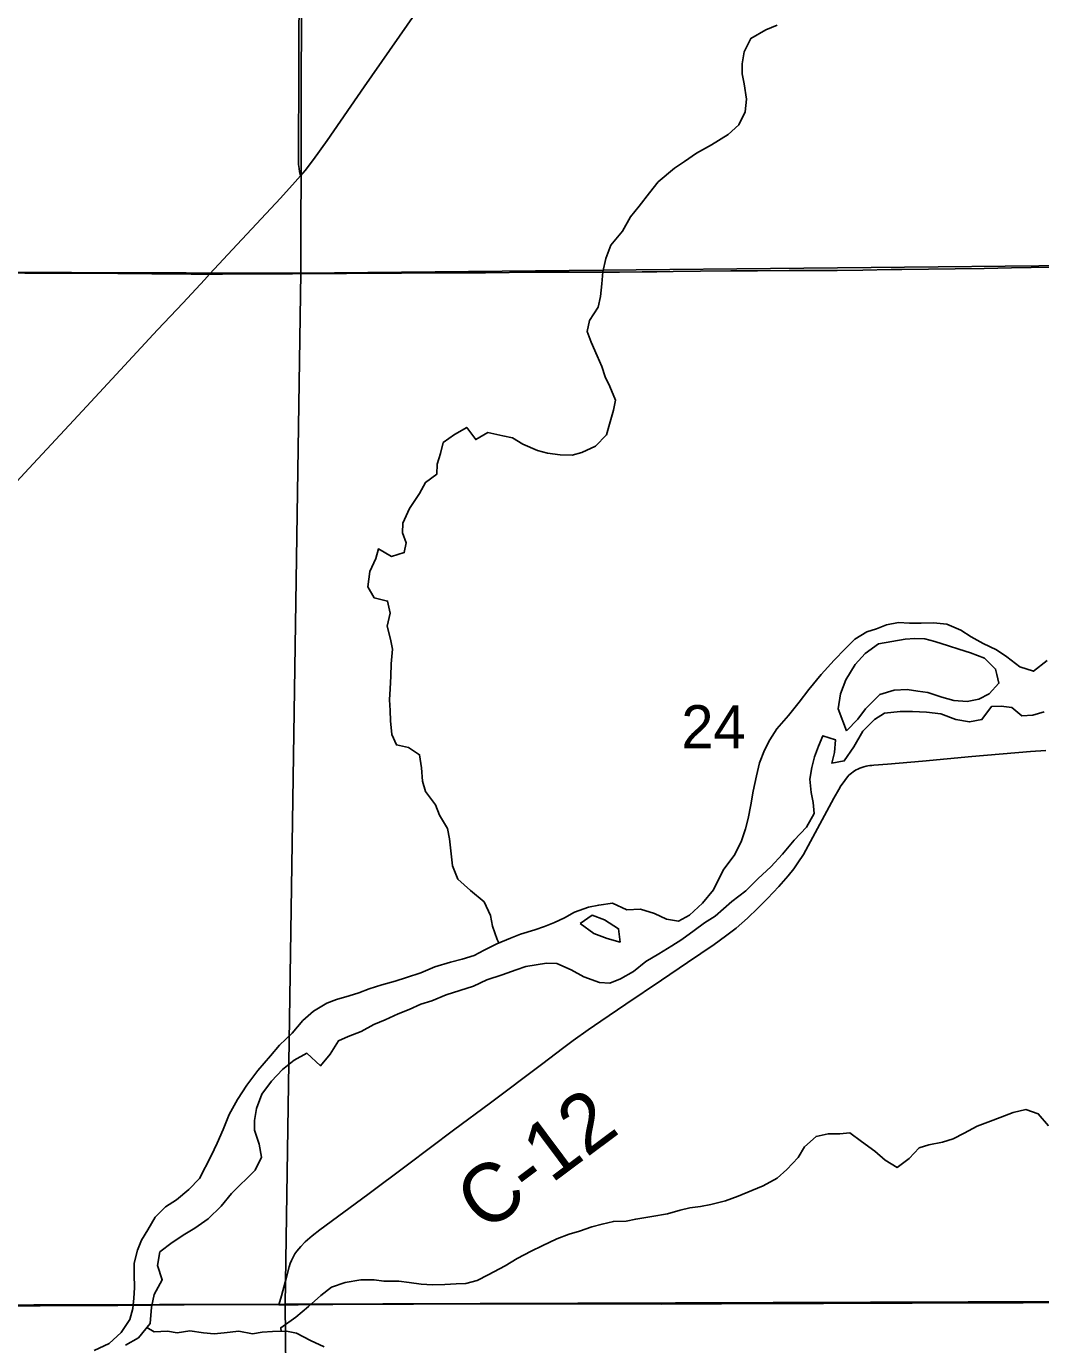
# Model space of a CAD drawing. Extents: x 0 to 34, y 0 to 22.
# Drawn here: x 7.827 to 8.318, y 15.384 to 16.023 of the extents above; entities that cross this region are included whole.
import ezdxf

# ---------------------------------------------------------------- set-up
doc = ezdxf.new("R2010")
doc.units = 0
for name, color, linetype in [('GM_X_County_Road', 7, 'Continuous'), ('GM_X_County_Road_Text', 7, 'Continuous'), ('GM_X_Major_River', 7, 'Continuous'), ('GM_X_Minor_River', 7, 'Continuous'), ('GM_X_Section', 7, 'Continuous'), ('GM_X_Section_Text', 7, 'Continuous'), ('GM_X_State_Route', 7, 'Continuous'), ('GM_X_Township_Road', 7, 'Continuous')]:
    doc.layers.add(name, color=color, linetype=linetype)

msp = doc.modelspace()

# ---------------------------------------------------------------- linework, layer by layer
at = {"layer": 'GM_X_County_Road'}
for points in [[(7.94893, 15.40341), (7.95008, 15.40765), (7.95252, 15.4167), (7.95388, 15.42176), (7.95439, 15.42337), (7.95494, 15.42484), (7.95542, 15.42586), (7.95593, 15.42682), (7.95665, 15.42805), (7.95754, 15.42931), (7.95849, 15.43047), (7.95952, 15.43167), (7.96167, 15.43386), (7.96501, 15.43676), (7.96866, 15.43967), (7.99189, 15.45686), (8.01111, 15.47111), (8.03348, 15.4879), (8.05145, 15.50124), (8.07602, 15.51975), (8.08691, 15.52801), (8.0914, 15.53135), (8.09872, 15.53659), (8.10487, 15.54082), (8.11698, 15.54898), (8.13419, 15.5607), (8.14685, 15.56917), (8.1597, 15.57784), (8.16525, 15.58186), (8.17029, 15.58587), (8.1758, 15.59062), (8.18083, 15.59547), (8.18558, 15.60011), (8.19106, 15.60605), (8.19553, 15.61122), (8.19822, 15.61463), (8.20023, 15.61739), (8.20295, 15.62156), (8.20866, 15.63207), (8.21319, 15.6404), (8.21772, 15.64879), (8.22011, 15.65302), (8.22113, 15.65472), (8.22215, 15.65622), (8.22302, 15.65742), (8.22385, 15.65851), (8.22442, 15.65926), (8.225, 15.65985), (8.2256, 15.66038), (8.22627, 15.66094), (8.22701, 15.66149), (8.22771, 15.66199), (8.22849, 15.66246), (8.22932, 15.66289), (8.23026, 15.66334), (8.23117, 15.66366), (8.23219, 15.66397), (8.23332, 15.66427), (8.2342, 15.66444), (8.23511, 15.66457), (8.23607, 15.66466), (8.23706, 15.66473), (8.24359, 15.66523), (8.26066, 15.66677), (8.28449, 15.66903), (8.31299, 15.67131), (8.32039, 15.67192)], [(7.58622, 15.40079), (7.6173, 15.40146), (7.62818, 15.40159), (7.64528, 15.40177), (7.65552, 15.40181), (7.6717, 15.40199), (7.70553, 15.40236), (7.7254, 15.40252), (7.74529, 15.40247), (7.76115, 15.40249), (7.78539, 15.40253), (7.80342, 15.40249), (7.83325, 15.40291), (7.84848, 15.40298), (7.87086, 15.40303), (7.91902, 15.40347), (7.92896, 15.40346), (7.94893, 15.40341)], [(7.94893, 15.40341), (7.95818, 15.40339), (7.97496, 15.40349), (8.00013, 15.40368), (8.01412, 15.40375), (8.02313, 15.4038), (8.06011, 15.40377), (8.08684, 15.40376), (8.13409, 15.40374), (8.14652, 15.40384), (8.1633, 15.40388), (8.18412, 15.40395), (8.21272, 15.40404), (8.25561, 15.40413), (8.28637, 15.40433), (8.30937, 15.4044), (8.33205, 15.4045)]]:
    msp.add_lwpolyline(points, dxfattribs=at)
at = {"layer": 'GM_X_Major_River'}
for points in [[(8.32105, 15.71539), (8.31438, 15.7103), (8.30775, 15.71241), (8.3015, 15.71719), (8.29639, 15.72062), (8.28996, 15.72369), (8.28427, 15.72694), (8.27916, 15.73019), (8.27234, 15.73306), (8.26589, 15.73366), (8.26001, 15.73349), (8.25431, 15.73352), (8.249, 15.73392), (8.24311, 15.73281), (8.23836, 15.73074), (8.23361, 15.72943), (8.2279, 15.72585), (8.22314, 15.72113), (8.2178, 15.71565), (8.21151, 15.70865), (8.20559, 15.70147), (8.20082, 15.69522), (8.19567, 15.6888), (8.19014, 15.68237), (8.1867, 15.67707), (8.18402, 15.67196), (8.18172, 15.66589), (8.18017, 15.65964), (8.17862, 15.65224), (8.17746, 15.6456), (8.1761, 15.63897), (8.17494, 15.63385), (8.17283, 15.6276), (8.16938, 15.62097), (8.16442, 15.61435), (8.16174, 15.60943), (8.15944, 15.60431), (8.1541, 15.59788), (8.14781, 15.59203), (8.14249, 15.5892), (8.13661, 15.59018), (8.13074, 15.59286), (8.1241, 15.59497), (8.11746, 15.59462), (8.11045, 15.59788), (8.1038, 15.59696), (8.09886, 15.59603), (8.09202, 15.59359), (8.08727, 15.59077), (8.08232, 15.58851), (8.07757, 15.58663), (8.07282, 15.58494), (8.06598, 15.58289), (8.06103, 15.58101), (8.05438, 15.57819), (8.04829, 15.57518), (8.04354, 15.57254), (8.03765, 15.57086), (8.03195, 15.56937), (8.02435, 15.56712), (8.01769, 15.56412), (8.01066, 15.56187), (8.00515, 15.56018), (7.99869, 15.55831)], [(8.29664, 15.70861), (8.29598, 15.71133), (8.29068, 15.71666), (8.28386, 15.71916), (8.27818, 15.72089), (8.27325, 15.72262), (8.26661, 15.72474), (8.26169, 15.7259), (8.25694, 15.72611), (8.25219, 15.72575), (8.23928, 15.72353), (8.23281, 15.71881), (8.22804, 15.71352), (8.22345, 15.70613), (8.22096, 15.69931), (8.21979, 15.69211), (8.22373, 15.68146)], [(8.22373, 15.68146), (8.22926, 15.68713), (8.23307, 15.69205), (8.23993, 15.69904), (8.24697, 15.7011), (8.25323, 15.70145), (8.25835, 15.70067), (8.26328, 15.69989), (8.26992, 15.69777), (8.27579, 15.69604), (8.28224, 15.69563), (8.28794, 15.69675), (8.29289, 15.69938), (8.29766, 15.70449), (8.29664, 15.70861)], [(8.02295, 15.55062), (8.02998, 15.55344), (8.04309, 15.55774), (8.04956, 15.56075), (8.05697, 15.56319), (8.06381, 15.56563), (8.06857, 15.56731), (8.07844, 15.56879), (8.08357, 15.56877), (8.09039, 15.5657), (8.09663, 15.56226), (8.10421, 15.55957), (8.10915, 15.55917), (8.11428, 15.56124), (8.12056, 15.56482), (8.12665, 15.56972), (8.13293, 15.5733), (8.13921, 15.57726), (8.14397, 15.58028), (8.15006, 15.58462), (8.15501, 15.58839), (8.16015, 15.59159), (8.16834, 15.59877), (8.175, 15.60387), (8.1811, 15.60991), (8.1872, 15.61558), (8.19273, 15.62163), (8.19845, 15.62844), (8.20436, 15.63467), (8.20819, 15.6413), (8.20764, 15.64661), (8.20671, 15.65155), (8.20598, 15.65801), (8.20695, 15.6637), (8.2083, 15.66881), (8.21022, 15.67393), (8.21233, 15.67904), (8.2184, 15.67712), (8.21799, 15.67086), (8.21664, 15.66574), (8.22272, 15.66685), (8.2273, 15.67367), (8.2317, 15.68124), (8.23742, 15.68691), (8.24217, 15.68992), (8.24977, 15.69084), (8.25584, 15.69081), (8.26248, 15.69041), (8.2695, 15.68962), (8.2767, 15.68693), (8.28334, 15.68576), (8.28942, 15.68687), (8.294, 15.69312), (8.29875, 15.69329), (8.30387, 15.6927), (8.30879, 15.68869), (8.3141, 15.68905), (8.31961, 15.69054)], [(8.11373, 15.58288), (8.11343, 15.58553), (8.10662, 15.58992), (8.10055, 15.59204), (8.09485, 15.58808)], [(8.09485, 15.58808), (8.10147, 15.5833), (8.10791, 15.58081), (8.11417, 15.57908), (8.11373, 15.58288)], [(7.99869, 15.55831), (7.99261, 15.55644), (7.98766, 15.55456), (7.98291, 15.55307), (7.97683, 15.55119), (7.97208, 15.54951), (7.96561, 15.54555), (7.96047, 15.54102), (7.95532, 15.53496), (7.94922, 15.52911), (7.94483, 15.524), (7.93873, 15.51682), (7.93338, 15.50982), (7.9288, 15.50282), (7.92479, 15.49562), (7.92191, 15.48823), (7.91903, 15.4816), (7.91616, 15.47554), (7.91042, 15.46456), (7.90527, 15.45927), (7.89937, 15.45417), (7.89404, 15.45078), (7.8889, 15.44586), (7.88545, 15.43962), (7.8824, 15.43469), (7.88048, 15.42977), (7.87874, 15.42351), (7.87872, 15.4182), (7.87888, 15.41156), (7.87867, 15.40662), (7.87808, 15.4015), (7.87673, 15.39619), (7.87253, 15.38995), (7.86662, 15.38466), (7.8594, 15.38128)], [(7.87459, 15.38387), (7.88087, 15.38745), (7.88659, 15.39425), (7.88719, 15.40222), (7.88855, 15.40829), (7.89237, 15.41549), (7.89013, 15.42233), (7.89129, 15.42896), (7.89719, 15.43349), (7.90329, 15.43764), (7.90823, 15.44047), (7.9147, 15.44499), (7.92099, 15.45123), (7.92595, 15.45728), (7.93739, 15.46862), (7.94045, 15.47487), (7.93934, 15.48114), (7.93709, 15.48798), (7.93711, 15.49272), (7.93808, 15.49841), (7.94058, 15.50542), (7.94535, 15.51167), (7.95069, 15.51734), (7.95621, 15.52187), (7.96249, 15.52526), (7.9691, 15.51916), (7.97368, 15.52483), (7.9777, 15.53126), (7.98245, 15.53333), (7.98872, 15.53577), (7.99481, 15.53916), (8.00032, 15.54142), (8.0066, 15.54424), (8.01192, 15.54649), (8.01763, 15.54893), (8.02295, 15.55062)]]:
    msp.add_lwpolyline(points, dxfattribs=at)
at = {"layer": 'GM_X_Minor_River'}
for points in [[(8.05546, 15.57865), (8.05458, 15.58028), (8.05233, 15.58674), (8.0514, 15.59187), (8.04839, 15.59852), (8.04177, 15.60405), (8.03553, 15.60958), (8.0329, 15.61605), (8.03217, 15.62326), (8.03144, 15.62915), (8.03051, 15.63409), (8.02674, 15.64055), (8.02468, 15.6455), (8.01996, 15.65197), (8.01846, 15.6571), (8.01792, 15.66355), (8.017, 15.66982), (8.0117, 15.67326), (8.00582, 15.67461), (8.00356, 15.67956), (8.00302, 15.6862), (8.00285, 15.69133), (8.00249, 15.69645), (8.00271, 15.70176), (8.00311, 15.70783), (8.00333, 15.71391), (8.00393, 15.72092), (8.003, 15.72586), (8.00132, 15.73213), (8.00286, 15.73839), (8.00156, 15.74428), (7.99511, 15.74582), (7.99191, 15.75115), (7.99289, 15.75855), (7.99576, 15.7648), (7.99711, 15.76953), (8.00336, 15.7659), (8.00963, 15.76777), (8.0106, 15.77251), (8.00872, 15.77727), (8.00893, 15.78201), (8.01218, 15.78902), (8.01696, 15.7964), (8.01983, 15.8017), (8.02535, 15.80566), (8.02556, 15.81059), (8.0271, 15.81571), (8.02845, 15.82102), (8.03397, 15.82498), (8.03987, 15.82837), (8.04421, 15.82247), (8.05011, 15.82586), (8.05731, 15.82431), (8.06205, 15.82334), (8.06698, 15.82028), (8.07418, 15.81722), (8.07891, 15.81587), (8.08517, 15.81508), (8.09087, 15.81487), (8.09562, 15.81618), (8.10227, 15.81937), (8.10761, 15.82485), (8.10896, 15.82997), (8.11089, 15.8368), (8.11186, 15.84154), (8.10923, 15.84819), (8.10697, 15.85294), (8.10528, 15.85788), (8.10303, 15.86302), (8.10021, 15.86967), (8.09814, 15.8748), (8.0993, 15.88011), (8.10351, 15.88655), (8.10467, 15.89186), (8.10526, 15.89793), (8.10586, 15.9038), (8.10721, 15.91025), (8.10971, 15.91669), (8.11524, 15.9235), (8.11926, 15.93031), (8.12345, 15.93561), (8.12841, 15.94204), (8.13261, 15.94734), (8.14042, 15.95394), (8.14537, 15.95715), (8.15108, 15.9613), (8.1585, 15.96525), (8.16649, 15.97034), (8.17164, 15.97487), (8.1747, 15.98131), (8.1753, 15.98738), (8.17419, 15.99479), (8.17326, 15.99973), (8.17328, 16.00447), (8.17426, 16.01035), (8.17751, 16.01679), (8.18474, 16.02093), (8.19025, 16.02318)], [(7.95001, 15.3905), (7.94978, 15.39228), (7.95702, 15.39737), (7.9633, 15.40247), (7.96921, 15.40795), (7.97435, 15.41191), (7.981, 15.41416), (7.9886, 15.41546), (7.99505, 15.41543), (7.99979, 15.41484), (8.007, 15.41481), (8.01194, 15.41422), (8.01782, 15.41343), (8.02332, 15.41303), (8.0292, 15.4132), (8.03471, 15.41355), (8.03945, 15.41372), (8.04496, 15.41522), (8.05029, 15.41785), (8.05847, 15.42218), (8.06437, 15.42576), (8.07102, 15.42934), (8.07635, 15.43197), (8.08357, 15.43536), (8.08947, 15.43761), (8.09441, 15.43911), (8.10049, 15.44117), (8.10543, 15.44248), (8.11094, 15.44378), (8.11701, 15.44395), (8.12176, 15.44487), (8.12955, 15.44617), (8.13715, 15.44747), (8.14323, 15.44915), (8.14798, 15.45027), (8.1531, 15.451), (8.15804, 15.45193), (8.16526, 15.4538), (8.17134, 15.45605), (8.178, 15.45868), (8.18351, 15.46093), (8.19017, 15.4647), (8.19493, 15.46885), (8.20046, 15.47471), (8.20352, 15.47982), (8.20905, 15.48492), (8.21493, 15.48623), (8.22063, 15.4862), (8.22537, 15.48675), (8.23105, 15.48255), (8.23748, 15.47778), (8.24259, 15.47339), (8.24827, 15.46995), (8.25417, 15.47429), (8.25894, 15.4794), (8.26369, 15.48089), (8.27034, 15.48219), (8.27547, 15.48369), (8.28079, 15.48651), (8.28707, 15.4899), (8.29353, 15.49234), (8.29829, 15.49403), (8.30456, 15.49647), (8.31064, 15.49796), (8.3167, 15.49585), (8.32161, 15.49013)], [(7.885, 15.39236), (7.88847, 15.39026), (7.89493, 15.39061), (7.89967, 15.38983), (7.90575, 15.39076), (7.91238, 15.38978), (7.91751, 15.38938), (7.92244, 15.38974), (7.92947, 15.39066), (7.93611, 15.3893), (7.94085, 15.39004), (7.94579, 15.3904), (7.95262, 15.39056), (7.95736, 15.38959), (7.96418, 15.38615), (7.97081, 15.38308)]]:
    msp.add_lwpolyline(points, dxfattribs=at)
at = {"layer": 'GM_X_Section'}
for points in [[(7.46886, 16.40612), (7.96072, 16.40422), (7.95951, 15.90308), (7.45989, 15.90447)], [(7.96072, 16.40422), (8.48728, 16.40835), (8.47945, 15.90819), (7.95951, 15.90308)], [(7.95951, 15.90308), (8.47945, 15.90819), (8.47178, 15.40539), (7.95187, 15.40369)], [(7.45989, 15.90447), (7.95951, 15.90308), (7.95187, 15.40369), (7.46474, 15.40235)], [(7.46474, 15.40235), (7.95187, 15.40369), (7.95709, 14.90157), (7.46088, 14.90162)], [(7.95187, 15.40369), (8.47178, 15.40539), (8.46562, 14.9022), (7.95709, 14.90157)]]:
    msp.add_lwpolyline(points, close=True, dxfattribs=at)
at = {"layer": 'GM_X_State_Route'}
msp.add_lwpolyline([(7.80397, 15.78299), (7.82775, 15.80842), (7.85161, 15.83419), (7.87, 15.85402), (7.89006, 15.87568), (7.90246, 15.88876), (7.91283, 15.89993), (7.91534, 15.90264), (7.92869, 15.917), (7.94974, 15.93945), (7.95683, 15.9473), (7.95929, 15.95023), (7.96154, 15.9529), (7.96568, 15.95818), (7.97219, 15.96729), (7.99026, 15.99335), (8.02815, 16.04801)], dxfattribs=at)
at = {"layer": 'GM_X_Township_Road'}
for points in [[(7.95929, 15.95023), (7.95893, 15.95236), (7.95868, 15.9538), (7.95855, 15.9548), (7.95846, 15.95567), (7.95839, 15.95692), (7.95838, 15.9678), (7.95851, 15.99298), (7.95862, 16.01659), (7.95887, 16.05327)], [(7.46092, 15.90412), (7.4686, 15.90411), (7.48119, 15.90409), (7.50015, 15.90405), (7.53403, 15.9039), (7.56573, 15.9038), (7.60157, 15.90375), (7.64374, 15.90369), (7.67048, 15.90364), (7.70125, 15.90365), (7.72145, 15.90358), (7.73962, 15.90347), (7.76739, 15.90332), (7.79356, 15.90319), (7.82588, 15.90306), (7.85168, 15.90302), (7.87095, 15.9029), (7.88742, 15.90272), (7.90637, 15.90267), (7.91534, 15.90264)], [(7.91534, 15.90264), (7.92164, 15.90269), (7.92844, 15.90273), (7.95552, 15.90282), (7.98159, 15.90291), (8.00832, 15.90312), (8.03162, 15.90328), (8.049, 15.90327), (8.07204, 15.90356), (8.09691, 15.90359), (8.11383, 15.90365), (8.12487, 15.90371), (8.13201, 15.90373), (8.13978, 15.90386), (8.15314, 15.90409), (8.16777, 15.90419), (8.18074, 15.90429), (8.19607, 15.90436), (8.21398, 15.90444), (8.21926, 15.90446), (8.23169, 15.9046), (8.24537, 15.90482), (8.25065, 15.9049), (8.27644, 15.90515), (8.29043, 15.90537), (8.30379, 15.9056), (8.32275, 15.90592)]]:
    msp.add_lwpolyline(points, dxfattribs=at)

# ---------------------------------------------------------------- texts
at = {"layer": 'GM_X_County_Road_Text'}
msp.add_text('C-12', height=0.028409, rotation=36.73086, dxfattribs=at).set_placement((8.04876, 15.43786))
at = {"layer": 'GM_X_Section_Text'}
msp.add_text('24', height=0.020928, rotation=0.00001, dxfattribs=at).set_placement((8.14382, 15.6729))

doc.saveas('drawing.dxf')
